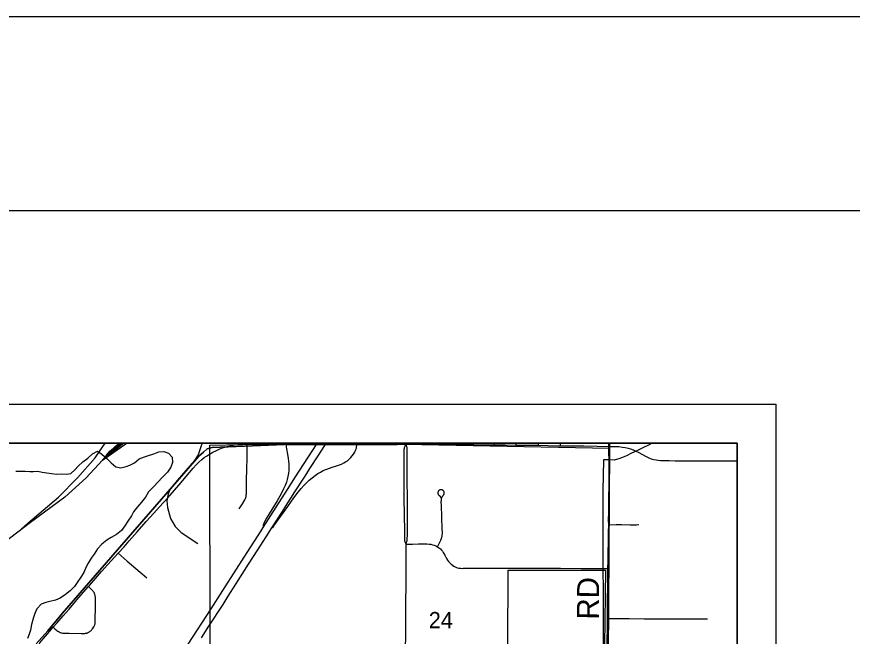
# Model space of a CAD drawing. Extents: x 0 to 34, y 0 to 22.
# Drawn here: x 7.043 to 9.197, y 20.401 to 22 of the extents above; entities that cross this region are included whole.
import ezdxf

# ---------------------------------------------------------------- set-up
doc = ezdxf.new("R2010")
doc.units = 0
for name, color, linetype in [('GM_X_City_Street', 7, 'Continuous'), ('GM_X_Corporation', 7, 'Continuous'), ('GM_X_County_Road', 7, 'Continuous'), ('GM_X_County_Road_Text', 7, 'Continuous'), ('GM_X_Interchange_Ramps', 7, 'Continuous'), ('GM_X_Interstate_Route', 7, 'Continuous'), ('GM_X_Minor_River', 7, 'Continuous'), ('GM_X_Rail_Line', 7, 'Continuous'), ('GM_X_Section_Text', 7, 'Continuous'), ('GM_X_Township_Road', 7, 'Continuous'), ('SH_Border', 7, 'Continuous'), ('SH_Cut_Line', 7, 'Continuous'), ('SH_Data', 7, 'Continuous')]:
    doc.layers.add(name, color=color, linetype=linetype)

msp = doc.modelspace()

# ---------------------------------------------------------------- linework, layer by layer
at = {"layer": 'GM_X_City_Street'}
for p, q in [((8.22, 20.8963), (8.22, 20.9)), ((8.2746, 20.8955), (8.2747, 20.9)), ((8.3303, 20.8945), (8.3303, 20.9))]:
    msp.add_line(p, q, dxfattribs=at)
for points in [[(7.6164, 20.7305), (7.6244, 20.7431), (7.6304, 20.7533), (7.6316, 20.7554), (7.6323, 20.7568), (7.6328, 20.7578), (7.6331, 20.7585), (7.6333, 20.7593), (7.6336, 20.7603), (7.6339, 20.7613), (7.6341, 20.7625), (7.6343, 20.7639), (7.6344, 20.7652), (7.6346, 20.7669), (7.6347, 20.7685), (7.6347, 20.7699), (7.6352, 20.7888), (7.6355, 20.7991), (7.6363, 20.8376), (7.6367, 20.8569), (7.6371, 20.8793), (7.6371, 20.8886), (7.6371, 20.8969)], [(8.3876, 20.8943), (8.3876, 20.8993), (8.3876, 20.9)], [(8.4446, 20.8931), (8.4446, 20.8952), (8.4446, 20.9)], [(8.1273, 20.6324), (8.132, 20.6411), (8.1346, 20.6458), (8.1364, 20.6498), (8.1373, 20.6519), (8.1381, 20.6544), (8.1385, 20.6559), (8.139, 20.6579), (8.1394, 20.6597), (8.1397, 20.6621), (8.14, 20.6676), (8.14, 20.6721), (8.1399, 20.6762), (8.1387, 20.7104), (8.1375, 20.7377), (8.1373, 20.7496), (8.1374, 20.7519), (8.1375, 20.7538), (8.1376, 20.7553), (8.138, 20.757), (8.1386, 20.7592), (8.1393, 20.7609), (8.1397, 20.7615), (8.1401, 20.7623), (8.1406, 20.7629), (8.1411, 20.7635), (8.1417, 20.7641), (8.1424, 20.7649), (8.1428, 20.7654), (8.1433, 20.7661), (8.1439, 20.7671), (8.1443, 20.7681), (8.1446, 20.7693), (8.1448, 20.7704), (8.1448, 20.7716), (8.1447, 20.7726), (8.1444, 20.7738), (8.1441, 20.7748), (8.1435, 20.7757), (8.143, 20.7764), (8.1423, 20.7772), (8.1418, 20.7777), (8.1412, 20.7781), (8.1406, 20.7785), (8.1395, 20.7789), (8.1387, 20.7791), (8.1379, 20.7793), (8.1369, 20.7795), (8.1361, 20.7795), (8.1353, 20.7794), (8.1345, 20.7792), (8.1338, 20.7789), (8.1329, 20.7786), (8.132, 20.7781), (8.1311, 20.7775), (8.1303, 20.7767), (8.1297, 20.7759), (8.1292, 20.7752), (8.1289, 20.7745), (8.1286, 20.7737), (8.1285, 20.7729), (8.1284, 20.7721), (8.1284, 20.7712), (8.1285, 20.7704), (8.1287, 20.7697), (8.1289, 20.7689), (8.1292, 20.7682), (8.1296, 20.7673), (8.1303, 20.7662), (8.1311, 20.7653), (8.1319, 20.7645), (8.138, 20.7581)], [(8.5691, 20.6891), (8.5885, 20.6895), (8.6015, 20.6896), (8.6239, 20.6893), (8.6405, 20.6894), (8.6467, 20.6898)], [(8.0467, 20.6395), (8.0628, 20.6395), (8.0789, 20.6398), (8.089, 20.6399), (8.0952, 20.6398), (8.1004, 20.6396), (8.1057, 20.6392), (8.1101, 20.6387), (8.1145, 20.6378), (8.1187, 20.6365), (8.1228, 20.6348), (8.1273, 20.6324), (8.1305, 20.6303), (8.1349, 20.6267), (8.1376, 20.624), (8.1401, 20.6211), (8.1425, 20.6174), (8.1462, 20.6108), (8.1507, 20.602), (8.1533, 20.5978), (8.1558, 20.5944), (8.1591, 20.5908), (8.1627, 20.5875), (8.1661, 20.5849), (8.1698, 20.5826), (8.1729, 20.5808), (8.1764, 20.5792), (8.179, 20.5782), (8.1825, 20.5774), (8.185, 20.577), (8.1876, 20.5768), (8.1919, 20.5767), (8.1942, 20.5768), (8.2294, 20.577), (8.2454, 20.5771), (8.2712, 20.5773), (8.2937, 20.5772), (8.3089, 20.5771), (8.3263, 20.577), (8.3437, 20.577), (8.363, 20.5771), (8.3941, 20.5768), (8.4444, 20.5768), (8.4978, 20.5765), (8.5581, 20.5763), (8.5672, 20.5762)], [(7.3046, 20.6155), (7.3279, 20.5955), (7.3607, 20.5668), (7.3662, 20.5623), (7.3783, 20.5526)], [(7.1371, 20.4251), (7.1395, 20.4224), (7.1418, 20.4201), (7.1441, 20.4181), (7.146, 20.4168), (7.1489, 20.4148), (7.1523, 20.4127), (7.155, 20.4114), (7.1578, 20.4105), (7.1608, 20.4099), (7.165, 20.4095), (7.178, 20.4092), (7.2092, 20.4089), (7.216, 20.4088), (7.2183, 20.4089), (7.2202, 20.4091), (7.2216, 20.4093), (7.2231, 20.4096), (7.2247, 20.4101), (7.226, 20.4106), (7.2273, 20.4112), (7.2286, 20.4119), (7.2299, 20.4127), (7.2311, 20.4136), (7.2325, 20.4146), (7.2339, 20.4159), (7.2353, 20.4175), (7.2367, 20.4191), (7.2383, 20.421), (7.2401, 20.4235), (7.2417, 20.426), (7.2426, 20.4277), (7.2433, 20.4293), (7.2439, 20.4307), (7.2442, 20.4321), (7.2446, 20.4336), (7.2449, 20.4356), (7.2452, 20.4405), (7.2454, 20.4543), (7.2456, 20.4675), (7.246, 20.4808), (7.246, 20.497), (7.2458, 20.5019), (7.2453, 20.5055), (7.2448, 20.5076), (7.2444, 20.5091), (7.2437, 20.5108), (7.243, 20.5124), (7.2421, 20.5142), (7.2412, 20.5155), (7.2401, 20.5171), (7.2391, 20.5185), (7.2358, 20.5221), (7.2332, 20.5247), (7.2282, 20.5298)], [(8.5659, 20.4472), (8.571, 20.4472), (8.5881, 20.4471), (8.6216, 20.4471), (8.6602, 20.4469), (8.6757, 20.4469), (8.7012, 20.4467), (8.7261, 20.4468), (8.7422, 20.4465), (8.782, 20.4467), (8.805, 20.4468), (8.8237, 20.4467)]]:
    msp.add_lwpolyline(points, dxfattribs=at)
at = {"layer": 'GM_X_Corporation'}
for points in [[(2.1, 14.1), (8.9, 14.1), (8.9, 20.9), (5.8906, 20.9)], [(7.0932, 20.3819), (7.1229, 20.4155), (7.1608, 20.461), (7.5121, 20.8658), (7.5239, 20.8764), (7.5334, 20.8851), (7.547, 20.8884), (7.7955, 20.8985), (7.7955, 20.9), (5.8906, 20.9)], [(8.565, 20.3824), (8.5654, 20.4308), (8.5657, 20.4477), (8.5661, 20.4802), (8.5667, 20.5469), (8.567, 20.5767), (8.5675, 20.5943), (8.5686, 20.6684), (8.5689, 20.6897), (8.5687, 20.7008), (8.5689, 20.7204), (8.5698, 20.8286), (8.5698, 20.8479), (8.5695, 20.8852), (8.5695, 20.892), (8.5695, 20.8988), (8.5695, 20.9), (5.8906, 20.9)], [(8.9, 20.3511), (8.9, 20.9), (7.7955, 20.9), (7.7955, 20.8985), (7.547, 20.8884), (7.5334, 20.8851), (7.5239, 20.8764), (7.5121, 20.8658), (7.1608, 20.461), (7.1229, 20.4155), (7.0932, 20.3819)], [(8.9, 14.3789), (8.9, 20.9), (8.5695, 20.9), (8.5695, 20.8988), (8.5695, 20.892), (8.5695, 20.8852), (8.5698, 20.8479), (8.5698, 20.8286), (8.5689, 20.7204), (8.5687, 20.7008), (8.5689, 20.6897), (8.5686, 20.6684), (8.5675, 20.5943), (8.567, 20.5767), (8.5667, 20.5469), (8.5661, 20.4802), (8.5657, 20.4477), (8.5654, 20.4308), (8.565, 20.3824)], [(8.3087, 20.3771), (8.3095, 20.5721), (8.5605, 20.5722), (8.5584, 20.3778)]]:
    msp.add_lwpolyline(points, dxfattribs=at)
for points in [[(7.7961, 20.8998), (8.0431, 20.8969), (8.5706, 20.8869), (8.5677, 20.3491), (8.5695, 19.8537), (7.5413, 19.8609), (7.5417, 20.3812), (7.5405, 20.8943)], [(8.5707, 20.9), (8.0431, 20.9), (8.0431, 20.8969), (8.5706, 20.8869)], [(8.9, 20.349), (8.9, 20.9), (8.5707, 20.9), (8.5706, 20.8869), (8.5677, 20.3491)]]:
    msp.add_lwpolyline(points, close=True, dxfattribs=at)
at = {"layer": 'GM_X_County_Road'}
msp.add_line((8.046, 20.8968), (8.046, 20.9), dxfattribs=at)
for points in [[(8.0467, 20.6395), (8.0442, 20.6455), (8.0434, 20.648), (8.0431, 20.6507), (8.043, 20.6628), (8.0429, 20.6727), (8.0414, 20.7577), (8.0416, 20.803), (8.0418, 20.8707), (8.042, 20.8846), (8.0422, 20.8871), (8.0426, 20.8887), (8.0431, 20.8902), (8.0438, 20.8917), (8.046, 20.8968)], [(8.0467, 20.6395), (8.0488, 20.6457), (8.0492, 20.6479), (8.0494, 20.6499), (8.0496, 20.6518), (8.05, 20.6629), (8.05, 20.7037), (8.05, 20.718), (8.0499, 20.7518), (8.0489, 20.8105), (8.049, 20.8391), (8.049, 20.8478), (8.049, 20.8571), (8.0491, 20.8671), (8.0494, 20.8859), (8.0491, 20.8888), (8.0486, 20.8906), (8.0477, 20.893), (8.046, 20.8968)], [(8.5697, 20.8915), (8.5697, 20.8983), (8.5698, 20.9)], [(8.5691, 20.6891), (8.569, 20.7002), (8.5691, 20.7198), (8.5701, 20.828), (8.57, 20.8473), (8.5697, 20.8846), (8.5697, 20.8915)], [(8.5672, 20.5762), (8.5678, 20.5937), (8.5688, 20.6679), (8.5691, 20.6891)], [(8.0454, 20.3754), (8.0458, 20.3992), (8.046, 20.4477), (8.046, 20.4825), (8.0463, 20.5398), (8.0465, 20.5935), (8.0465, 20.6202), (8.0465, 20.6273), (8.0467, 20.6395)], [(8.5659, 20.4472), (8.5663, 20.4797), (8.567, 20.5463), (8.5672, 20.5762)], [(8.5654, 20.405), (8.5657, 20.4302), (8.5659, 20.4472)], [(8.5649, 20.3505), (8.5652, 20.3619), (8.5652, 20.3818), (8.5654, 20.405)]]:
    msp.add_lwpolyline(points, dxfattribs=at)
at = {"layer": 'GM_X_Interchange_Ramps'}
for p, q in [((7.7379, 20.9), (7.7375, 20.8965)), ((7.9193, 20.8962), (7.9195, 20.9))]:
    msp.add_line(p, q, dxfattribs=at)
for points in [[(7.7375, 20.8965), (7.7378, 20.8906), (7.7384, 20.8851), (7.741, 20.8714), (7.7429, 20.8604), (7.7438, 20.853), (7.7443, 20.8456), (7.7444, 20.8369), (7.7441, 20.8294), (7.7433, 20.822), (7.7418, 20.8134), (7.74, 20.8062), (7.7379, 20.7991), (7.7349, 20.7909), (7.7309, 20.7818), (7.7262, 20.7724), (7.7207, 20.7626), (7.7138, 20.7508), (7.6865, 20.7065), (7.6835, 20.7001), (7.6799, 20.6927), (7.679, 20.6904), (7.6784, 20.6887), (7.6779, 20.6866), (7.6778, 20.6845), (7.678, 20.6821)], [(7.8563, 20.8376), (7.8647, 20.8404), (7.8723, 20.8429), (7.8798, 20.8458), (7.8859, 20.8487), (7.8907, 20.8514), (7.8953, 20.8545), (7.9, 20.8585), (7.9038, 20.8624), (7.9074, 20.8666), (7.9109, 20.8716), (7.914, 20.8769), (7.917, 20.883), (7.9179, 20.8852), (7.9183, 20.887), (7.9193, 20.8962)], [(8.0131, 20.8966), (8.0083, 20.8988), (8.0054, 20.8999), (8.0051, 20.9)], [(7.7007, 20.6814), (7.7029, 20.683), (7.7043, 20.6841), (7.706, 20.6861), (7.7233, 20.711), (7.7413, 20.7365), (7.7508, 20.7503), (7.7593, 20.7618), (7.7686, 20.7735), (7.7762, 20.7826), (7.7836, 20.791), (7.79, 20.7977), (7.7968, 20.8041), (7.8044, 20.8106), (7.8118, 20.8162), (7.819, 20.8211), (7.8259, 20.8253), (7.8325, 20.8288), (7.8489, 20.8352), (7.8563, 20.8376)]]:
    msp.add_lwpolyline(points, dxfattribs=at)
at = {"layer": 'GM_X_Interstate_Route'}
for points in [[(7.678, 20.6821), (7.712, 20.735), (7.7409, 20.7801), (7.7615, 20.8126), (7.8153, 20.8966), (7.8175, 20.9)], [(7.8355, 20.8914), (7.8389, 20.8965), (7.8412, 20.9)], [(7.519, 20.3976), (7.5383, 20.4273), (7.5747, 20.4837), (7.588, 20.5048), (7.6079, 20.5363), (7.6139, 20.5458), (7.6403, 20.5872), (7.6646, 20.6248), (7.6784, 20.6462), (7.6861, 20.6583), (7.7007, 20.6814), (7.7168, 20.7066), (7.7208, 20.7129), (7.728, 20.7238), (7.7372, 20.7385), (7.7495, 20.758), (7.76, 20.7742), (7.7664, 20.7841), (7.7778, 20.8019), (7.7828, 20.8097), (7.7905, 20.8218), (7.7986, 20.8344), (7.8214, 20.87), (7.8355, 20.8914)], [(7.4851, 20.3811), (7.5439, 20.4721), (7.5741, 20.5192), (7.6094, 20.5748), (7.6288, 20.6052), (7.6727, 20.6738), (7.678, 20.6821)]]:
    msp.add_lwpolyline(points, dxfattribs=at)
at = {"layer": 'GM_X_Minor_River'}
for points in [[(8.6818, 20.9), (8.6812, 20.8998), (8.6713, 20.8946), (8.6603, 20.889), (8.6496, 20.8846), (8.6394, 20.8794), (8.628, 20.8739), (8.615, 20.8668), (8.5979, 20.8602), (8.5831, 20.8562), (8.5703, 20.8564), (8.5556, 20.857)], [(7.0407, 20.8274), (7.0505, 20.8273), (7.0645, 20.8275), (7.0766, 20.8269), (7.0864, 20.8268), (7.097, 20.8271), (7.1083, 20.825), (7.1207, 20.8233), (7.1328, 20.8217), (7.1452, 20.82), (7.1573, 20.8202), (7.1705, 20.8197), (7.1823, 20.8211), (7.193, 20.8308), (7.2014, 20.8406), (7.2133, 20.8514), (7.2258, 20.8611), (7.2381, 20.8723), (7.2506, 20.879), (7.2626, 20.8709), (7.275, 20.8605), (7.2865, 20.849), (7.2985, 20.8386), (7.3113, 20.8358), (7.3245, 20.8398), (7.334, 20.8427), (7.3466, 20.849)], [(7.3466, 20.849), (7.3588, 20.8591), (7.3721, 20.8646), (7.3827, 20.8683), (7.3964, 20.8726), (7.4093, 20.877), (7.4221, 20.8784), (7.4338, 20.8741), (7.4431, 20.8637), (7.4444, 20.85), (7.4401, 20.8379), (7.4313, 20.8251), (7.4179, 20.8109), (7.4071, 20.7996), (7.3953, 20.7873), (7.3826, 20.7741), (7.3745, 20.7602), (7.3645, 20.7471), (7.3545, 20.7354), (7.3442, 20.7223), (7.3384, 20.7125), (7.3291, 20.6985), (7.3218, 20.6865), (7.3129, 20.6741), (7.2996, 20.664), (7.2863, 20.6566), (7.2748, 20.6491), (7.2622, 20.6387), (7.2511, 20.6274), (7.2426, 20.6131), (7.2349, 20.603), (7.2268, 20.5905), (7.2218, 20.5803), (7.2156, 20.5664), (7.2078, 20.5536), (7.1982, 20.5404), (7.192, 20.5302), (7.1806, 20.519), (7.1687, 20.5089), (7.155, 20.4996), (7.1425, 20.4944), (7.1284, 20.4908), (7.1182, 20.4887), (7.1061, 20.4839), (7.095, 20.4719), (7.0899, 20.4606), (7.0848, 20.447), (7.0808, 20.4315), (7.078, 20.4174), (7.0745, 20.4065), (7.0709, 20.3955)], [(8.5556, 20.857), (8.5541, 20.7765), (8.554, 20.6532), (8.5547, 20.441), (8.5535, 20.2661), (8.5523, 20.057), (8.5522, 19.9109), (8.5514, 19.673)]]:
    msp.add_lwpolyline(points, dxfattribs=at)
at = {"layer": 'GM_X_Rail_Line'}
msp.add_line((7.3059, 20.9), (7.2926, 20.8868), dxfattribs=at)
for points in [[(7.3192, 20.9), (7.2637, 20.8561), (7.2219, 20.8105), (7.1668, 20.7601), (7.1145, 20.7221), (7.0749, 20.6923), (7.0133, 20.6452)], [(7.0469, 20.6709), (7.0717, 20.6935), (7.1506, 20.7601), (7.1991, 20.8105), (7.2447, 20.8618), (7.2706, 20.9)], [(7.2744, 20.8689), (7.2637, 20.8561), (7.3247, 20.8989), (7.3261, 20.9)], [(7.2744, 20.8689), (7.314, 20.8995), (7.3146, 20.9)], [(7.2926, 20.8868), (7.3027, 20.8948), (7.3098, 20.9)], [(7.5208, 20.9), (7.5182, 20.8928), (7.5103, 20.8692), (7.5014, 20.8553), (7.4564, 20.8034), (7.4383, 20.781), (7.4331, 20.7689), (7.4298, 20.7511), (7.4314, 20.7337), (7.4393, 20.7057), (7.4511, 20.6844), (7.4663, 20.6689), (7.5097, 20.6406)], [(7.2744, 20.8689), (7.2827, 20.8788), (7.2926, 20.8868)]]:
    msp.add_lwpolyline(points, dxfattribs=at)
at = {"layer": 'GM_X_Township_Road'}
for p, q in [((7.6769, 20.8971), (7.7375, 20.8965)), ((8.046, 20.8968), (8.063, 20.897))]:
    msp.add_line(p, q, dxfattribs=at)
for points in [[(7.3046, 20.6155), (7.3197, 20.6323), (7.3327, 20.6473), (7.3531, 20.6708), (7.3766, 20.6973), (7.3959, 20.7193), (7.4106, 20.7354), (7.432, 20.7587), (7.4663, 20.7981), (7.4787, 20.8128), (7.4977, 20.835), (7.5058, 20.8437), (7.5125, 20.8504), (7.5204, 20.8575), (7.5263, 20.8623), (7.5319, 20.8663), (7.5398, 20.8714), (7.5485, 20.8765), (7.5558, 20.8802), (7.5643, 20.8841), (7.5731, 20.8876), (7.5797, 20.8898), (7.5876, 20.892), (7.5968, 20.894), (7.6055, 20.8954), (7.6136, 20.8962), (7.6243, 20.8968), (7.6371, 20.8969)], [(7.6371, 20.8969), (7.6419, 20.897), (7.6686, 20.897), (7.6769, 20.8971)], [(7.7375, 20.8965), (7.754, 20.8962), (7.7876, 20.8965), (7.8153, 20.8966), (7.8187, 20.8966), (7.8358, 20.8965)], [(7.8358, 20.8965), (7.8389, 20.8965), (7.8572, 20.8965), (7.8877, 20.8965), (7.9193, 20.8962)], [(7.9193, 20.8962), (7.9219, 20.8962), (7.9629, 20.8964), (7.9915, 20.8964), (8.0131, 20.8966)], [(8.0131, 20.8966), (8.0238, 20.8966), (8.046, 20.8968)], [(8.063, 20.897), (8.068, 20.897), (8.1134, 20.8977), (8.1594, 20.8974), (8.2004, 20.8965), (8.22, 20.8963)], [(8.22, 20.8963), (8.2583, 20.8957), (8.2746, 20.8955)], [(8.2746, 20.8955), (8.3018, 20.895), (8.3291, 20.8945), (8.3303, 20.8945)], [(8.3303, 20.8945), (8.3658, 20.8944), (8.3876, 20.8943)], [(8.3876, 20.8943), (8.3888, 20.8943), (8.4118, 20.8937), (8.4392, 20.8932), (8.4446, 20.8931)], [(8.4446, 20.8931), (8.4647, 20.8926), (8.5045, 20.8925), (8.5387, 20.8919), (8.5685, 20.8915), (8.5697, 20.8915)], [(8.5697, 20.8915), (8.5853, 20.8912), (8.5953, 20.8907), (8.6046, 20.8898), (8.6114, 20.8886), (8.6188, 20.8869), (8.6253, 20.8848), (8.6318, 20.8823), (8.6386, 20.8793), (8.6466, 20.8752), (8.6633, 20.8664), (8.6685, 20.864), (8.6741, 20.8613), (8.6782, 20.8597), (8.6853, 20.8576), (8.6914, 20.8566), (8.6965, 20.8559), (8.7026, 20.8554), (8.7126, 20.8549), (8.7171, 20.8548), (8.725, 20.8546), (8.74, 20.8542), (8.7716, 20.8541), (8.7916, 20.8542), (8.8429, 20.8545), (8.864, 20.8545), (8.8788, 20.8543), (8.9, 20.8543)], [(7.2282, 20.5298), (7.2307, 20.5327), (7.2617, 20.5684), (7.2861, 20.5957), (7.3046, 20.6155)], [(7.1371, 20.4251), (7.1462, 20.4354), (7.1621, 20.454), (7.1776, 20.4718), (7.1942, 20.4911), (7.2031, 20.5015), (7.2282, 20.5298)], [(7.1004, 20.3815), (7.1026, 20.3843), (7.1062, 20.3887), (7.1121, 20.3957), (7.1272, 20.4139), (7.1371, 20.4251)]]:
    msp.add_lwpolyline(points, dxfattribs=at)
at = {"layer": 'SH_Border'}
msp.add_lwpolyline([(1.5, 21.5), (33.5, 21.5), (33.5, 0.5), (1.5, 0.5)], close=True, dxfattribs=at)
at = {"layer": 'SH_Cut_Line'}
msp.add_lwpolyline([(0, 0), (34, 0), (34, 22), (0, 22)], close=True, dxfattribs=at)
at = {"layer": 'SH_Data'}
for p, q in [((2, 21), (9, 21)), ((2, 21), (9, 21)), ((9, 21), (9, 14)), ((9, 21), (9, 14)), ((2.1, 20.9), (8.9, 20.9)), ((2.1, 20.9), (8.9, 20.9)), ((8.9, 20.9), (8.9, 14.1)), ((8.9, 20.9), (8.9, 14.1))]:
    msp.add_line(p, q, dxfattribs=at)

# ---------------------------------------------------------------- texts
at = {"layer": 'GM_X_County_Road_Text'}
msp.add_text('RD', height=0.05682, rotation=89.5122, dxfattribs=at).set_placement((8.5435, 20.4443))
at = {"layer": 'GM_X_Section_Text'}
msp.add_text('24', height=0.04186, rotation=0, dxfattribs=at).set_placement((8.105, 20.4223))

doc.saveas('drawing.dxf')
